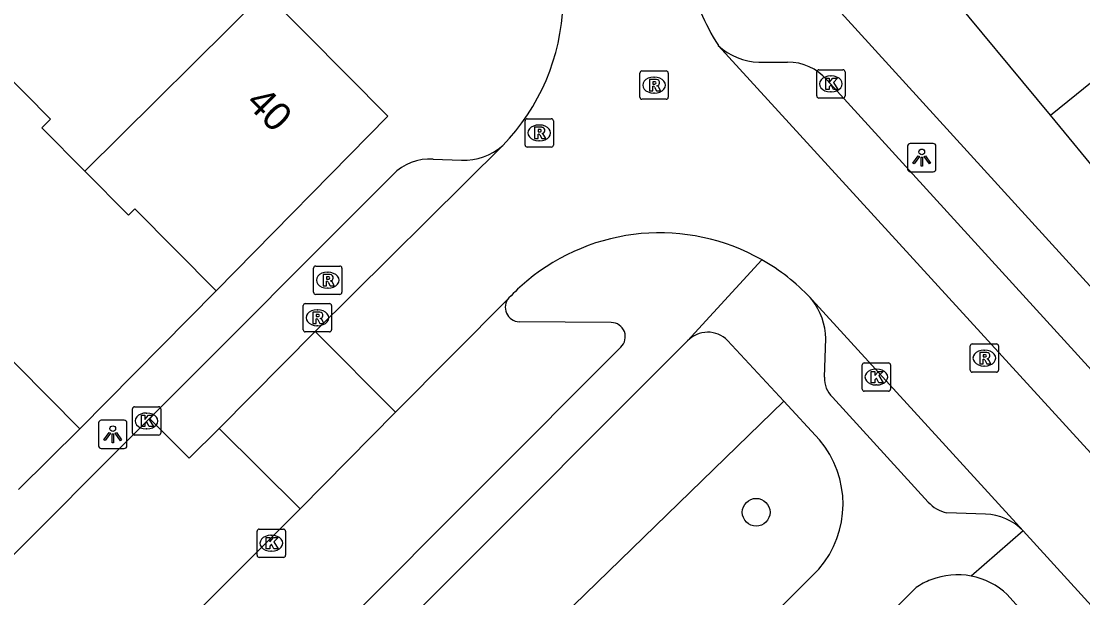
# Model space of a CAD drawing. Extents: x 159040 to 160094, y 381214 to 382518.
# Drawn here: x 159596.64 to 159634.1, y 381884.61 to 381904.94 of the extents above; entities that cross this region are included whole.
import ezdxf

# ---------------------------------------------------------------- set-up
doc = ezdxf.new("R2010")
doc.units = 0
for name, color, linetype in [('IMGEO_Boom', 7, 'Continuous'), ('IMGEO_Groenvoorziening', 7, 'Continuous'), ('IMGEO_Kolk', 7, 'Continuous'), ('IMGEO_Lichtpunt', 7, 'Continuous'), ('IMGEO_Muur', 7, 'Continuous'), ('IMGEO_Pand', 7, 'Continuous'), ('IMGEO_Pand_nummerreeks', 7, 'Continuous'), ('IMGEO_Rijbaan_lokaal_open', 7, 'Continuous'), ('IMGEO_Rioolput', 7, 'Continuous'), ('IMGEO_Voetpad_open', 7, 'Continuous')]:
    doc.layers.add(name, color=color, linetype=linetype)

msp = doc.modelspace()

# ---------------------------------------------------------------- linework, layer by layer
at = {"layer": 'IMGEO_Boom'}
msp.add_circle((159622.571, 381887.628), 0.489, dxfattribs=at)
at = {"layer": 'IMGEO_Groenvoorziening'}
msp.add_lwpolyline([(159604.997, 381873.534), (159623.542, 381891.545)], dxfattribs=at)
at = {"layer": 'IMGEO_Kolk'}
for p, q in [((159624.707, 381902.305), (159624.707, 381903.157)), ((159624.782, 381903.231), (159625.634, 381903.231)), ((159625.708, 381903.157), (159625.708, 381902.305)), ((159625.195, 381903.011), (159625.22, 381903.011)), ((159625.218, 381902.451), (159625.193, 381902.451)), ((159625.634, 381902.231), (159624.782, 381902.231)), ((159626.311, 381891.969), (159626.311, 381892.821)), ((159626.386, 381892.895), (159627.238, 381892.895)), ((159626.799, 381892.675), (159626.824, 381892.675)), ((159627.312, 381892.821), (159627.312, 381891.969)), ((159627.238, 381891.895), (159626.386, 381891.895)), ((159626.822, 381892.115), (159626.797, 381892.115)), ((159600.559, 381890.42), (159600.559, 381891.272)), ((159600.634, 381891.346), (159601.486, 381891.346)), ((159601.047, 381891.126), (159601.072, 381891.126)), ((159601.56, 381891.272), (159601.56, 381890.42)), ((159601.486, 381890.346), (159600.634, 381890.346)), ((159601.07, 381890.566), (159601.045, 381890.566)), ((159604.962, 381886.109), (159604.962, 381886.961)), ((159605.037, 381887.035), (159605.889, 381887.035)), ((159605.963, 381886.961), (159605.963, 381886.109)), ((159605.45, 381886.815), (159605.475, 381886.815)), ((159605.473, 381886.255), (159605.448, 381886.255)), ((159605.889, 381886.035), (159605.037, 381886.035))]:
    msp.add_line(p, q, dxfattribs=at)
for points in [[(159624.707, 381902.305), (159624.707, 381903.157)], [(159624.782, 381903.231), (159625.634, 381903.231)], [(159625.708, 381903.157), (159625.708, 381902.305)], [(159625.028, 381902.931), (159625.151, 381902.931), (159625.151, 381902.78), (159625.281, 381902.931), (159625.445, 381902.931), (159625.299, 381902.78), (159625.452, 381902.531), (159625.3, 381902.531), (159625.215, 381902.695), (159625.151, 381902.628), (159625.151, 381902.531), (159625.028, 381902.531), (159625.028, 381902.931)], [(159625.634, 381902.231), (159624.782, 381902.231)], [(159626.311, 381891.969), (159626.311, 381892.821)], [(159626.386, 381892.895), (159627.238, 381892.895)], [(159626.632, 381892.595), (159626.755, 381892.595), (159626.755, 381892.444), (159626.885, 381892.595), (159627.049, 381892.595), (159626.903, 381892.444), (159627.056, 381892.195), (159626.904, 381892.195), (159626.819, 381892.359), (159626.755, 381892.292), (159626.755, 381892.195), (159626.632, 381892.195), (159626.632, 381892.595)], [(159627.312, 381892.821), (159627.312, 381891.969)], [(159627.238, 381891.895), (159626.386, 381891.895)], [(159600.559, 381890.42), (159600.559, 381891.272)], [(159600.634, 381891.346), (159601.486, 381891.346)], [(159601.56, 381891.272), (159601.56, 381890.42)], [(159600.88, 381891.046), (159601.003, 381891.046), (159601.003, 381890.895), (159601.133, 381891.046), (159601.297, 381891.046), (159601.151, 381890.895), (159601.304, 381890.646), (159601.152, 381890.646), (159601.067, 381890.81), (159601.003, 381890.743), (159601.003, 381890.646), (159600.88, 381890.646), (159600.88, 381891.046)], [(159601.486, 381890.346), (159600.634, 381890.346)], [(159604.962, 381886.109), (159604.962, 381886.961)], [(159605.037, 381887.035), (159605.889, 381887.035)], [(159605.963, 381886.961), (159605.963, 381886.109)], [(159605.283, 381886.735), (159605.406, 381886.735), (159605.406, 381886.584), (159605.536, 381886.735), (159605.7, 381886.735), (159605.554, 381886.584), (159605.707, 381886.335), (159605.555, 381886.335), (159605.47, 381886.499), (159605.406, 381886.432), (159605.406, 381886.335), (159605.283, 381886.335), (159605.283, 381886.735)], [(159605.889, 381886.035), (159605.037, 381886.035)]]:
    msp.add_lwpolyline(points, dxfattribs=at)
for centre, start, end in [((159624.784, 381903.155), 91.552, 178.448), ((159624.784, 381903.155), 91.552, 178.448), ((159625.632, 381903.155), 1.552, 88.448), ((159625.632, 381903.155), 1.552, 88.448), ((159624.784, 381902.307), 181.552, 268.448), ((159624.784, 381902.307), 181.552, 268.448), ((159625.632, 381902.307), 271.552, 358.448), ((159625.632, 381902.307), 271.552, 358.448), ((159626.388, 381892.819), 91.552, 178.448), ((159626.388, 381892.819), 91.552, 178.448), ((159627.236, 381892.819), 1.552, 88.448), ((159627.236, 381892.819), 1.552, 88.448), ((159626.388, 381891.971), 181.552, 268.448), ((159626.388, 381891.971), 181.552, 268.448), ((159627.236, 381891.971), 271.552, 358.448), ((159627.236, 381891.971), 271.552, 358.448), ((159600.636, 381891.27), 91.552, 178.448), ((159600.636, 381891.27), 91.552, 178.448), ((159601.484, 381891.27), 1.552, 88.448), ((159601.484, 381891.27), 1.552, 88.448), ((159600.636, 381890.422), 181.552, 268.448), ((159600.636, 381890.422), 181.552, 268.448), ((159601.484, 381890.422), 271.552, 358.448), ((159601.484, 381890.422), 271.552, 358.448), ((159605.039, 381886.959), 91.552, 178.448), ((159605.039, 381886.959), 91.552, 178.448), ((159605.887, 381886.959), 1.552, 88.448), ((159605.887, 381886.959), 1.552, 88.448), ((159605.039, 381886.111), 181.552, 268.448), ((159605.039, 381886.111), 181.552, 268.448), ((159605.887, 381886.111), 271.552, 358.448), ((159605.887, 381886.111), 271.552, 358.448)]:
    msp.add_arc(centre, 0.0765, start, end, dxfattribs=at)
for centre, major_axis, ratio, start_param, end_param in [((159625.194, 381902.731), (-0.387, 0.002), 0.722429, 4.712389, 7.853982), ((159625.219, 381902.731), (-0.39, 0.002), 0.717154, 1.570796, 4.712389), ((159626.798, 381892.395), (-0.387, 0.002), 0.722429, 4.712389, 7.853982), ((159626.823, 381892.395), (-0.39, 0.002), 0.717154, 1.570796, 4.712389), ((159601.046, 381890.846), (-0.387, 0.002), 0.722429, 4.712389, 7.853982), ((159601.071, 381890.846), (-0.39, 0.002), 0.717154, 1.570796, 4.712389), ((159605.449, 381886.535), (-0.387, 0.002), 0.722429, 4.712389, 7.853982), ((159605.474, 381886.535), (-0.39, 0.002), 0.717154, 1.570796, 4.712389)]:
    msp.add_ellipse(centre, major_axis=major_axis, ratio=ratio, start_param=start_param, end_param=end_param, dxfattribs=at)
at = {"layer": 'IMGEO_Lichtpunt'}
for p, q in [((159627.917, 381900.535), (159627.917, 381899.728)), ((159627.917, 381900.535), (159627.917, 381899.728)), ((159628.819, 381900.63), (159628.011, 381900.63)), ((159628.819, 381900.63), (159628.011, 381900.63)), ((159628.913, 381899.728), (159628.913, 381900.535)), ((159628.913, 381899.728), (159628.913, 381900.535)), ((159628.011, 381899.634), (159628.819, 381899.634)), ((159628.011, 381899.634), (159628.819, 381899.634)), ((159599.37, 381890.778), (159599.37, 381889.971)), ((159599.37, 381890.778), (159599.37, 381889.971)), ((159600.272, 381890.873), (159599.464, 381890.873)), ((159600.272, 381890.873), (159599.464, 381890.873)), ((159600.366, 381889.971), (159600.366, 381890.778)), ((159600.366, 381889.971), (159600.366, 381890.778)), ((159599.464, 381889.877), (159600.272, 381889.877)), ((159599.464, 381889.877), (159600.272, 381889.877))]:
    msp.add_line(p, q, dxfattribs=at)
for points in [[(159628.291, 381900.199), (159628.33, 381900.171), (159628.142, 381899.909), (159628.104, 381899.936), (159628.291, 381900.199)], [(159628.393, 381900.151), (159628.44, 381900.151), (159628.44, 381899.829), (159628.393, 381899.829), (159628.393, 381900.151)], [(159628.503, 381900.171), (159628.541, 381900.198), (159628.728, 381899.936), (159628.689, 381899.908), (159628.503, 381900.171)], [(159599.744, 381890.442), (159599.783, 381890.414), (159599.595, 381890.152), (159599.557, 381890.179), (159599.744, 381890.442)], [(159599.846, 381890.394), (159599.893, 381890.394), (159599.893, 381890.072), (159599.846, 381890.072), (159599.846, 381890.394)], [(159599.956, 381890.414), (159599.994, 381890.441), (159600.181, 381890.179), (159600.142, 381890.151), (159599.956, 381890.414)]]:
    msp.add_lwpolyline(points, dxfattribs=at)
for centre in [(159628.416, 381900.333), (159599.869, 381890.576)]:
    msp.add_circle(centre, 0.0994, dxfattribs=at)
for centre, start, end in [((159628.011, 381900.535), 90, 180), ((159628.011, 381900.535), 90, 180), ((159628.819, 381900.535), 0, 90), ((159628.819, 381900.535), 0, 90), ((159628.011, 381899.728), 180, 270), ((159628.011, 381899.728), 180, 270), ((159628.819, 381899.728), 270, 0), ((159628.819, 381899.728), 270, 360), ((159599.464, 381890.778), 90, 180), ((159599.464, 381890.778), 90, 180), ((159600.272, 381890.778), 0, 90), ((159600.272, 381890.778), 0, 90), ((159599.464, 381889.971), 180, 270), ((159599.464, 381889.971), 180, 270), ((159600.272, 381889.971), 270, 0), ((159600.272, 381889.971), 270, 360)]:
    msp.add_arc(centre, 0.0946, start, end, dxfattribs=at)
at = {"layer": 'IMGEO_Muur'}
msp.add_lwpolyline([(159598.702, 381890.571), (159603.517, 381895.43)], dxfattribs=at)
at = {"layer": 'IMGEO_Pand'}
for points in [[(159632.954, 381901.623), (159639.504, 381906.927)], [(159632.954, 381901.623), (159629.113, 381906.267)], [(159598.882, 381899.658), (159605.24, 381905.964)], [(159605.24, 381905.964), (159609.575, 381901.593), (159603.517, 381895.43)], [(159598.882, 381899.658), (159597.37, 381901.183), (159597.673, 381901.484), (159594.957, 381904.223)], [(159636.796, 381896.977), (159632.954, 381901.623)], [(159603.517, 381895.43), (159600.643, 381898.328), (159600.42, 381898.108), (159598.882, 381899.658)], [(159594.248, 381895.062), (159598.702, 381890.571)], [(159598.702, 381890.571), (159596.547, 381888.434)]]:
    msp.add_lwpolyline(points, dxfattribs=at)
at = {"layer": 'IMGEO_Rijbaan_lokaal_open'}
for points in [[(159640.475, 381885.985), (159639.012, 381884.641), (159621.236, 381904.086)], [(159613.627, 381900.56), (159607.009, 381893.996)], [(159613.845, 381895.182), (159609.846, 381891.159)], [(159624.549, 381895.115), (159624.476, 381895.195)], [(159624.549, 381895.115), (159631.99, 381886.975)], [(159603.619, 381890.584), (159607.009, 381893.996)], [(159607.009, 381893.996), (159609.846, 381891.159)], [(159609.846, 381891.159), (159606.476, 381887.753)], [(159589.196, 381878.96), (159594.035, 381883.801), (159599.887, 381889.654), (159601.163, 381890.932)], [(159601.163, 381890.932), (159602.567, 381889.529), (159603.619, 381890.584)], [(159606.476, 381887.753), (159603.619, 381890.584)], [(159606.476, 381887.753), (159577.251, 381858.509)], [(159648.596, 381868.82), (159647.997, 381869.474), (159641.863, 381876.151), (159631.99, 381886.975)]]:
    msp.add_lwpolyline(points, dxfattribs=at)
for centre, radius, start, end in [((159627.676, 381908.244), 7.665, 192.665, 212.8471), ((159608.273, 381905.79), 7.485, 315.6701, 358.1822), ((159619.167, 381890.168), 7.312, 60.4117, 129.8638), ((159619.191, 381890.199), 7.272, 43.391, 60.4586), ((159619.425, 381889.893), 7.689, 130.0294, 136.533)]:
    msp.add_arc(centre, radius, start, end, dxfattribs=at)
at = {"layer": 'IMGEO_Rioolput'}
for p, q in [((159618.467, 381902.262), (159618.467, 381903.114)), ((159618.542, 381903.188), (159619.394, 381903.188)), ((159619.468, 381903.114), (159619.468, 381902.262)), ((159618.955, 381902.968), (159618.98, 381902.968)), ((159618.978, 381902.408), (159618.953, 381902.408)), ((159619.394, 381902.188), (159618.542, 381902.188)), ((159614.416, 381900.576), (159614.416, 381901.428)), ((159614.491, 381901.502), (159615.343, 381901.502)), ((159614.904, 381901.282), (159614.929, 381901.282)), ((159615.417, 381901.428), (159615.417, 381900.576)), ((159615.343, 381900.502), (159614.491, 381900.502)), ((159614.927, 381900.722), (159614.902, 381900.722)), ((159607.028, 381896.309), (159607.88, 381896.309)), ((159606.953, 381895.383), (159606.953, 381896.235)), ((159607.441, 381896.089), (159607.466, 381896.089)), ((159607.954, 381896.235), (159607.954, 381895.383)), ((159607.88, 381895.309), (159607.028, 381895.309)), ((159607.464, 381895.529), (159607.439, 381895.529)), ((159606.587, 381894.06), (159606.587, 381894.912)), ((159606.662, 381894.986), (159607.514, 381894.986)), ((159607.588, 381894.912), (159607.588, 381894.06)), ((159607.075, 381894.766), (159607.1, 381894.766)), ((159607.098, 381894.206), (159607.073, 381894.206)), ((159607.514, 381893.986), (159606.662, 381893.986)), ((159630.122, 381892.638), (159630.122, 381893.49)), ((159630.197, 381893.564), (159631.049, 381893.564)), ((159630.61, 381893.344), (159630.635, 381893.344)), ((159631.123, 381893.49), (159631.123, 381892.638)), ((159631.049, 381892.564), (159630.197, 381892.564)), ((159630.633, 381892.784), (159630.608, 381892.784))]:
    msp.add_line(p, q, dxfattribs=at)
for points in [[(159618.467, 381902.262), (159618.467, 381903.114)], [(159618.542, 381903.188), (159619.394, 381903.188)], [(159619.468, 381903.114), (159619.468, 381902.262)], [(159619.056, 381902.886), (159618.804, 381902.888), (159618.804, 381902.488)], [(159618.982, 381902.807), (159618.928, 381902.807), (159618.928, 381902.726)], [(159618.928, 381902.726), (159618.98, 381902.726)], [(159618.804, 381902.488), (159618.928, 381902.488), (159618.928, 381902.65), (159618.939, 381902.65)], [(159618.986, 381902.621), (159619.057, 381902.488), (159619.197, 381902.488), (159619.132, 381902.614)], [(159619.394, 381902.188), (159618.542, 381902.188)], [(159614.416, 381900.576), (159614.416, 381901.428)], [(159614.491, 381901.502), (159615.343, 381901.502)], [(159615.005, 381901.2), (159614.753, 381901.202), (159614.753, 381900.802)], [(159615.417, 381901.428), (159615.417, 381900.576)], [(159614.753, 381900.802), (159614.877, 381900.802), (159614.877, 381900.964), (159614.888, 381900.964)], [(159614.931, 381901.121), (159614.877, 381901.121), (159614.877, 381901.04)], [(159614.877, 381901.04), (159614.929, 381901.04)], [(159614.935, 381900.935), (159615.006, 381900.802), (159615.146, 381900.802), (159615.081, 381900.928)], [(159615.343, 381900.502), (159614.491, 381900.502)], [(159607.028, 381896.309), (159607.88, 381896.309)], [(159606.953, 381895.383), (159606.953, 381896.235)], [(159607.542, 381896.007), (159607.29, 381896.009), (159607.29, 381895.609)], [(159607.468, 381895.928), (159607.414, 381895.928), (159607.414, 381895.847)], [(159607.954, 381896.235), (159607.954, 381895.383)], [(159607.29, 381895.609), (159607.414, 381895.609), (159607.414, 381895.771), (159607.425, 381895.771)], [(159607.414, 381895.847), (159607.466, 381895.847)], [(159607.472, 381895.742), (159607.543, 381895.609), (159607.683, 381895.609), (159607.618, 381895.735)], [(159607.88, 381895.309), (159607.028, 381895.309)], [(159606.587, 381894.06), (159606.587, 381894.912)], [(159606.662, 381894.986), (159607.514, 381894.986)], [(159607.588, 381894.912), (159607.588, 381894.06)], [(159607.176, 381894.684), (159606.924, 381894.686), (159606.924, 381894.286)], [(159606.924, 381894.286), (159607.048, 381894.286), (159607.048, 381894.448), (159607.059, 381894.448)], [(159607.102, 381894.605), (159607.048, 381894.605), (159607.048, 381894.524)], [(159607.048, 381894.524), (159607.1, 381894.524)], [(159607.106, 381894.419), (159607.177, 381894.286), (159607.317, 381894.286), (159607.252, 381894.412)], [(159607.514, 381893.986), (159606.662, 381893.986)], [(159630.122, 381892.638), (159630.122, 381893.49)], [(159630.197, 381893.564), (159631.049, 381893.564)], [(159631.123, 381893.49), (159631.123, 381892.638)], [(159630.711, 381893.262), (159630.459, 381893.264), (159630.459, 381892.864)], [(159630.459, 381892.864), (159630.583, 381892.864), (159630.583, 381893.026), (159630.594, 381893.026)], [(159630.637, 381893.183), (159630.583, 381893.183), (159630.583, 381893.102)], [(159630.583, 381893.102), (159630.635, 381893.102)], [(159630.641, 381892.997), (159630.712, 381892.864), (159630.852, 381892.864), (159630.787, 381892.99)], [(159631.049, 381892.564), (159630.197, 381892.564)]]:
    msp.add_lwpolyline(points, dxfattribs=at)
for centre, radius, start, end in [((159618.544, 381903.112), 0.0765, 91.552, 178.448), ((159618.544, 381903.112), 0.0765, 91.552, 178.448), ((159619.392, 381903.112), 0.0765, 1.552, 88.448), ((159619.392, 381903.112), 0.0765, 1.552, 88.448), ((159618.964, 381902.915), 0.19, 274.7715, 282.9687), ((159618.988, 381902.711), 0.0964, 77.0061, 93.1865), ((159619.002, 381902.768), 0.0378, 276.6634, 79.6772), ((159619.055, 381902.776), 0.109, 350.3612, 89.416), ((159619.053, 381902.776), 0.112, 277.5842, 350.9817), ((159619.037, 381902.561), 0.108, 29.5134, 73.7905), ((159618.938, 381902.597), 0.0533, 26.0293, 88.6989), ((159618.544, 381902.264), 0.0765, 181.552, 268.448), ((159618.544, 381902.264), 0.0765, 181.552, 268.448), ((159619.392, 381902.264), 0.0765, 271.552, 358.448), ((159619.392, 381902.264), 0.0765, 271.552, 358.448), ((159614.493, 381901.426), 0.0765, 91.552, 178.448), ((159614.493, 381901.426), 0.0765, 91.552, 178.448), ((159615.004, 381901.09), 0.109, 350.3612, 89.416), ((159615.341, 381901.426), 0.0765, 1.552, 88.448), ((159615.341, 381901.426), 0.0765, 1.552, 88.448), ((159614.887, 381900.911), 0.0533, 26.0293, 88.6989), ((159614.913, 381901.229), 0.19, 274.7715, 282.9687), ((159614.937, 381901.025), 0.0964, 77.0061, 93.1865), ((159614.951, 381901.082), 0.0378, 276.6634, 79.6772), ((159615.002, 381901.09), 0.112, 277.5842, 350.9817), ((159614.986, 381900.875), 0.108, 29.5134, 73.7905), ((159614.493, 381900.578), 0.0765, 181.552, 268.448), ((159614.493, 381900.578), 0.0765, 181.552, 268.448), ((159615.341, 381900.578), 0.0765, 271.552, 358.448), ((159615.341, 381900.578), 0.0765, 271.552, 358.448), ((159607.03, 381896.233), 0.0765, 91.552, 178.448), ((159607.03, 381896.233), 0.0765, 91.552, 178.448), ((159607.878, 381896.233), 0.0765, 1.552, 88.448), ((159607.878, 381896.233), 0.0765, 1.552, 88.448), ((159607.474, 381895.832), 0.0964, 77.0061, 93.1865), ((159607.488, 381895.889), 0.0378, 276.6634, 79.6772), ((159607.541, 381895.897), 0.109, 350.3612, 89.416), ((159607.424, 381895.718), 0.0533, 26.0293, 88.6989), ((159607.45, 381896.036), 0.19, 274.7715, 282.9687), ((159607.539, 381895.897), 0.112, 277.5842, 350.9817), ((159607.523, 381895.682), 0.108, 29.5134, 73.7905), ((159607.03, 381895.385), 0.0765, 181.552, 268.448), ((159607.03, 381895.385), 0.0765, 181.552, 268.448), ((159607.878, 381895.385), 0.0765, 271.552, 358.448), ((159607.878, 381895.385), 0.0765, 271.552, 358.448), ((159606.664, 381894.91), 0.0765, 91.552, 178.448), ((159606.664, 381894.91), 0.0765, 91.552, 178.448), ((159607.512, 381894.91), 0.0765, 1.552, 88.448), ((159607.512, 381894.91), 0.0765, 1.552, 88.448), ((159607.058, 381894.395), 0.0533, 26.0293, 88.6989), ((159607.084, 381894.713), 0.19, 274.7715, 282.9687), ((159607.108, 381894.509), 0.0964, 77.0061, 93.1865), ((159607.122, 381894.566), 0.0378, 276.6634, 79.6772), ((159607.175, 381894.574), 0.109, 350.3612, 89.416), ((159607.173, 381894.574), 0.112, 277.5842, 350.9817), ((159607.157, 381894.359), 0.108, 29.5134, 73.7905), ((159606.664, 381894.062), 0.0765, 181.552, 268.448), ((159606.664, 381894.062), 0.0765, 181.552, 268.448), ((159607.512, 381894.062), 0.0765, 271.552, 358.448), ((159607.512, 381894.062), 0.0765, 271.552, 358.448), ((159630.199, 381893.488), 0.0765, 91.552, 178.448), ((159630.199, 381893.488), 0.0765, 91.552, 178.448), ((159631.047, 381893.488), 0.0765, 1.552, 88.448), ((159631.047, 381893.488), 0.0765, 1.552, 88.448), ((159630.593, 381892.973), 0.0533, 26.0293, 88.6989), ((159630.619, 381893.291), 0.19, 274.7715, 282.9687), ((159630.643, 381893.087), 0.0964, 77.0061, 93.1865), ((159630.657, 381893.144), 0.0378, 276.6634, 79.6772), ((159630.71, 381893.152), 0.109, 350.3612, 89.416), ((159630.708, 381893.152), 0.112, 277.5842, 350.9817), ((159630.692, 381892.937), 0.108, 29.5134, 73.7905), ((159630.199, 381892.64), 0.0765, 181.552, 268.448), ((159630.199, 381892.64), 0.0765, 181.552, 268.448), ((159631.047, 381892.64), 0.0765, 271.552, 358.448), ((159631.047, 381892.64), 0.0765, 271.552, 358.448)]:
    msp.add_arc(centre, radius, start, end, dxfattribs=at)
for centre, major_axis, ratio, start_param, end_param in [((159618.954, 381902.688), (-0.387, 0.002), 0.722429, 4.712389, 7.853982), ((159618.979, 381902.688), (-0.39, 0.002), 0.717154, 1.570796, 4.712389), ((159614.903, 381901.002), (-0.387, 0.002), 0.722429, 4.712389, 7.853982), ((159614.928, 381901.002), (-0.39, 0.002), 0.717154, 1.570796, 4.712389), ((159607.44, 381895.809), (-0.387, 0.002), 0.722429, 4.712389, 7.853982), ((159607.465, 381895.809), (-0.39, 0.002), 0.717154, 1.570796, 4.712389), ((159607.074, 381894.486), (-0.387, 0.002), 0.722429, 4.712389, 7.853982), ((159607.099, 381894.486), (-0.39, 0.002), 0.717154, 1.570796, 4.712389), ((159630.609, 381893.064), (-0.387, 0.002), 0.722429, 4.712389, 7.853982), ((159630.634, 381893.064), (-0.39, 0.002), 0.717154, 1.570796, 4.712389)]:
    msp.add_ellipse(centre, major_axis=major_axis, ratio=ratio, start_param=start_param, end_param=end_param, dxfattribs=at)
at = {"layer": 'IMGEO_Voetpad_open'}
for points in [[(159625.093, 381905.776), (159642.752, 381886.384)], [(159622.67, 381903.494), (159623.681, 381903.5)], [(159625.068, 381902.872), (159640.475, 381885.985)], [(159611.177, 381900.078), (159612.172, 381900.041)], [(159601.163, 381890.932), (159609.75, 381899.524)], [(159622.777, 381896.526), (159620.154, 381893.672)], [(159598.702, 381890.571), (159603.517, 381895.43)], [(159617.459, 381894.318), (159614.208, 381894.345)], [(159620.154, 381893.672), (159620.13, 381893.646), (159602.517, 381876.025), (159604.997, 381873.534)], [(159621.56, 381893.687), (159623.542, 381891.545)], [(159624.98, 381892.387), (159625.028, 381893.75)], [(159583.589, 381859.199), (159617.794, 381893.446)], [(159623.542, 381891.545), (159624.806, 381890.179)], [(159628.637, 381887.989), (159625.26, 381891.688)], [(159630.66, 381887.557), (159629.298, 381887.611)], [(159631.99, 381886.975), (159630.161, 381885.378)], [(159624.784, 381885.626), (159608.831, 381869.683)], [(159583.549, 381850.107), (159588.472, 381845.228), (159628.214, 381884.971)], [(159631.433, 381884.728), (159640.914, 381874.2)]]:
    msp.add_lwpolyline(points, dxfattribs=at)
for centre, radius, start, end in [((159622.755, 381905.733), 2.241, 227.3152, 267.8201), ((159623.673, 381901.637), 1.863, 41.5175, 89.7628), ((159612.253, 381902.112), 2.073, 267.7513, 311.5114), ((159611.046, 381898.3), 1.782, 85.7863, 136.6488), ((159614.225, 381894.85), 0.505, 138.8737, 268.0182), ((159622.674, 381893.691), 2.354, 1.4461, 37.2275), ((159617.451, 381893.815), 0.504, 312.9491, 89.0819), ((159620.864, 381892.996), 0.981, 44.826, 136.3965), ((159625.919, 381892.358), 0.94, 178.2062, 225.4532), ((159622.143, 381887.915), 3.495, 319.0833, 40.363), ((159629.578, 381888.868), 1.288, 223.0444, 257.4285), ((159630.614, 381885.642), 1.916, 44.0976, 88.6346), ((159629.67, 381882.855), 2.568, 111.261, 124.5435), ((159629.674, 381882.848), 2.576, 79.0943, 111.2728), ((159629.672, 381882.851), 2.574, 46.8232, 79.0422)]:
    msp.add_arc(centre, radius, start, end, dxfattribs=at)

# ---------------------------------------------------------------- texts
at = {"layer": 'IMGEO_Pand_nummerreeks'}
msp.add_text('40', height=1, rotation=314.7618, dxfattribs=at).set_placement((159604.526, 381902.027))

doc.saveas('drawing.dxf')
